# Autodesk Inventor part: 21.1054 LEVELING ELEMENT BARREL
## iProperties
Created: 2006-12
Part Number: 21.1054 LEVELING ELEMENT BARREL
Document SubType Name: Modeling
Designer: Andy Moles
Material: Steel
Density: 7.85 g/cm^3
Author: Andy Moles
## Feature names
1. Extrusion1
2. Extrusion2
3. Extrusion3
4. Chamfer1
5. Extrusion4
